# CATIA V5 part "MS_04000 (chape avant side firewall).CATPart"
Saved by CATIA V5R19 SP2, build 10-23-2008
Part number: MS_04004 (chape avant side firewall)
Bounding box of the stored display mesh (mm): x -1135.589 to 0, y -273.336 to 0, z 0 to 136.263
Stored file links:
  D:\EPSA\GIT\ELIZ-2022\01 - Maquette CATIA\MS_Miscellanous_Finish_Assembly\MS_A0400 (Firewall)\MS_04000 (chape avant side firewall).CATPart
  D:\EPSA\GIT\ELIZ-2022\01 - Maquette CATIA\MS_Miscellanous_Finish_Assembly\MS_A0400 (Firewall)\MS_A0400 (FireWall).CATProduct
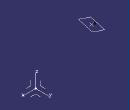
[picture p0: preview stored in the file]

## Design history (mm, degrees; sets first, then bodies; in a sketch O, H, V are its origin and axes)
AxisSystem1: origin (0, 0, 0), X (1, 0, 0), Y (0, 1, 0), Z (0, 0, 1)
Set1
  Point1: type OnCurve, Support DatumCurve1, Length 482.564
  Plane1: type Normal, Curve DatumCurve1, RefPoint Point1
  Sketch1 on Plane1, origin (-966.0201, -277.0747, 406.537), H (0.2757, -0.9612, 0), V (0.3605, 0.1034, 0.927)
    circle A1 centre (-36.6757, -304.8178) radius 14
    point P1 (-36.6757, -304.8178)
    reference projected point E1 (-36.6757, -304.8178) from Point1
    radius A1 = 14
    coincidence: P1 E1
Set2
  DatumCurve1: linked copy from another document
  DatumSurface1: linked copy from another document
Body1 (main body)
  Pad1: profile Sketch1, direction (-0.8911, -0.2556, 0.375), length 60
  Point2: type OnSurface, Support face of Pad1 from Sketch1.A1, Length 16.741, Direction (-0.5584, 0.6698, -0.4894)
  Plane2: type Tangent, Support face of Pad1 from Sketch1.A1, RefPoint Point2
  Point3: type OnSurface, Support Plane2, Length 1172.403, Direction (-0.9729, -0.1784, 0.147)
  Line1: type PtPt, FirstPoint Point3, SecondPoint Point2, End 25
Body2
  Sketch2 on face of DatumSurface1, origin (3.8523, -19.9899, -4.4703), H (-0.9819, -0.1892, 0), V (0.0406, -0.2106, 0.9767)
    reference intersected line E1 (1173.5132, 157.605) -> (1118.1117, 134.5686) from face of Pad1 from Sketch1.A1
    construction line L1 (1148.5377, 147.2199) -> (1158.5201, 123.2126)
    point P3 (1148.5377, 147.2199)
    reference projected point E2 (1147.6799, 149.2828) from Point2
    circle A1 centre (1158.5201, 123.2126) radius 1.7
    arc A2 centre (1158.5201, 123.2126) radius 7 from (1161.2077, 116.7491) to (1164.9836, 125.9002) ccw
    point P5 (1161.2077, 116.7491)
    point P6 (1164.9836, 125.9002)
    line L2 (1164.9836, 125.9002) -> (1155.0012, 149.9075)
    point P7 (1155.0012, 149.9075)
    line L3 (1155.0012, 149.9075) -> (1148.5377, 147.2199)
    point P8 (1148.5377, 147.2199)
    point P9 (1148.5377, 147.2199)
    point P10 (1142.0742, 144.5323)
    line L4 (1142.0742, 144.5323) -> (1148.5377, 147.2199)
    point P11 (1152.0566, 120.525)
    line L5 (1152.0566, 120.525) -> (1142.0742, 144.5323)
    point P12 (1161.2077, 116.7491)
    arc A3 centre (1158.5201, 123.2126) radius 7 from (1161.2077, 116.7491) to (1152.0566, 120.525) cw
    radius A1 = 1.7
    radius A2 = 7
    length L2 = 26
    coincidence: P3 E1, L1 E2, P5 L1, P7 E1, P5 P12, P8 P9
    perpendicularity: L1 E1
    tangency: L2 A2
    parallelism: L3 E1, L2 L1
    symmetry: P8 P9 L1, P7 P10 L1, L3 L4 L1, P6 P11 L1, L2 L5 L1, P5 P12 L1, A2 A3 L1
  Pad2: profile Sketch2, direction (0.1848, -0.9591, -0.2145), length 1.5
  Sketch3 on end face of Pad2, origin (4.1295, -21.4285, -4.792), H (0.9819, 0.1892, 0), V (0.0406, -0.2106, 0.9767)
    intersected line E1 (-1175.9339, 151.7834) -> (-1120.5324, 128.747) from face of Pad1 from Sketch1.A1
    intersected line E2 (-1171.0926, 163.4265) -> (-1115.6911, 140.3901) from face of Pad1 from Sketch1.A1
    point P1 (-1175.9339, 151.7834)
    point P2 (-1120.5324, 128.747)
    line L1 (-1171.0926, 163.4265) -> (-1175.9339, 151.7834)
    point P5 (-1175.9339, 151.7834)
    line L2 (-1115.6911, 140.3901) -> (-1120.5324, 128.747)
    point P6 (-1120.5324, 128.747)
    perpendicularity: L1 E1
    coincidence: P5 E1, P6 E1, P1 P5, P2 P6
    parallelism: L2 L1
  Pocket1: profile Sketch3, direction (-0.1848, 0.9591, 0.2145), up to start face of Pad2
